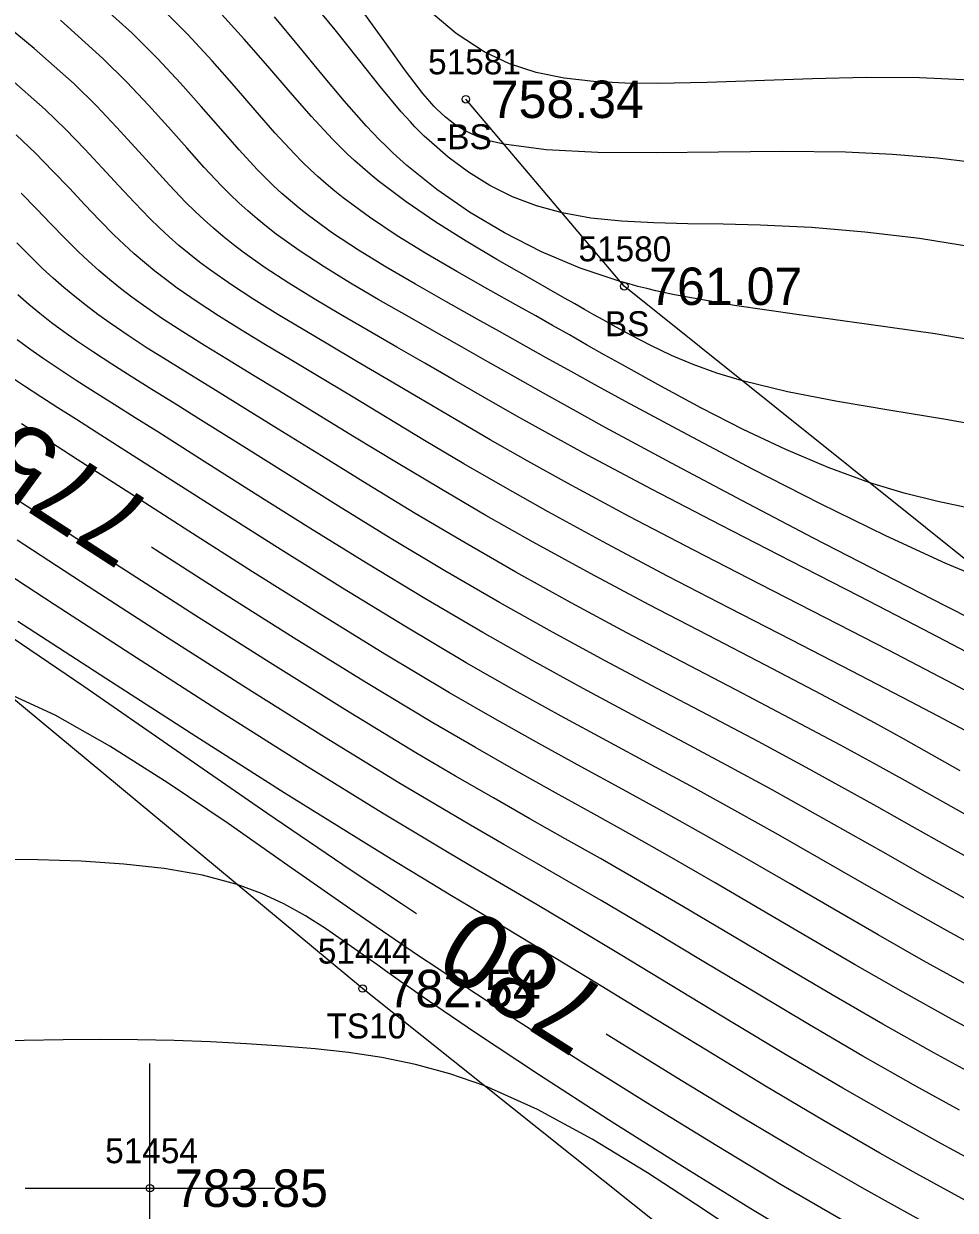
# Model space of a CAD drawing. Extents: x 1378535 to 1380697, y 997729 to 1000024.
# Drawn here: x 1379953.29 to 1379990.62, y 998733.56 to 998781.1 of the extents above; entities that cross this region are included whole.
import ezdxf

# ---------------------------------------------------------------- set-up
doc = ezdxf.new("R2010")
doc.units = 0
for name, color, linetype in [('RD_DTM_BkLn2', 7, 'Continuous'), ('RD_DTM_BkLn_txCode', 7, 'Continuous'), ('RD_DTM_Major1', 7, 'Continuous'), ('RD_DTM_Major1_Lbl', 7, 'Continuous'), ('RD_DTM_Minor1', 7, 'Continuous'), ('RD_EX_Misc', 7, 'Continuous'), ('RD_EX_Misc_txCode', 7, 'Continuous'), ('RD_EX_TX_Misc_ELEV', 7, 'Continuous'), ('RD_SMD_Locator', 7, 'Continuous')]:
    doc.layers.add(name, color=color, linetype=linetype)

msp = doc.modelspace()

# ---------------------------------------------------------------- linework, layer by layer
at = {"layer": 'RD_DTM_BkLn2'}
for points in [[(1380137.104, 998617.435), (1380114.932, 998627.982), (1380110.142, 998637.412), (1380109.582, 998648.354), (1380098.693, 998654.921), (1380088.864, 998651.688), (1380069.259, 998664.275), (1380051.712, 998676.601), (1380045.085, 998683.058), (1380025.38, 998678.361), (1380019.034, 998684.269), (1380023.868, 998692.688), (1380008.939, 998708.879), (1379966.873, 998742.441), (1379939.691, 998764.989), (1379904.79, 998796.424), (1379861.371, 998834.485), (1379829.578, 998867.997), (1379786.438, 998908.428), (1379759.831, 998933.444)], [(1380014.763, 998739.683), (1379995.467, 998756.083), (1379977.358, 998770.579), (1379971.008, 998778.071)]]:
    msp.add_lwpolyline(points, dxfattribs=at)
at = {"layer": 'RD_DTM_Major1'}
for points in [[(1379991.408, 998772.127), (1379989.19, 998772.491), (1379986.999, 998772.754), (1379984.861, 998772.929), (1379982.799, 998773.028), (1379981.321, 998773.063), (1379979.902, 998773.087), (1379978.544, 998773.121), (1379977.251, 998773.189), (1379976.024, 998773.314), (1379974.866, 998773.52), (1379973.845, 998773.801), (1379972.882, 998774.168), (1379971.974, 998774.618), (1379971.116, 998775.145), (1379970.305, 998775.746), (1379969.535, 998776.416), (1379969.345, 998776.598), (1379969.157, 998776.784), (1379968.971, 998776.974), (1379968.786, 998777.17), (1379968.602, 998777.37), (1379968.418, 998777.575), (1379967.574, 998778.578), (1379966.702, 998779.676), (1379965.773, 998780.855), (1379964.758, 998782.101)], [(1379992.409, 998756.662), (1379990.25, 998757.758), (1379987.715, 998759.057), (1379984.944, 998760.491), (1379982.074, 998761.992), (1379979.246, 998763.492), (1379976.597, 998764.924), (1379975.318, 998765.628), (1379974.116, 998766.298), (1379972.98, 998766.938), (1379971.897, 998767.552), (1379970.858, 998768.144), (1379969.85, 998768.716), (1379968.655, 998769.393), (1379967.499, 998770.054), (1379966.388, 998770.707), (1379965.331, 998771.356), (1379964.336, 998772.01), (1379963.41, 998772.673), (1379963.02, 998772.976), (1379962.643, 998773.283), (1379962.277, 998773.598), (1379961.919, 998773.923), (1379961.567, 998774.258), (1379961.218, 998774.607), (1379960.529, 998775.34), (1379959.824, 998776.127), (1379959.085, 998776.963), (1379958.292, 998777.842), (1379957.427, 998778.758), (1379956.469, 998779.705), (1379954.761, 998781.238)], [(1379991.217, 998749.311), (1379989.913, 998750.041), (1379988.628, 998750.76), (1379987.339, 998751.474), (1379986.025, 998752.191), (1379983.983, 998753.279), (1379981.859, 998754.391), (1379979.677, 998755.53), (1379977.46, 998756.696), (1379975.233, 998757.892), (1379973.018, 998759.118), (1379970.977, 998760.294), (1379968.985, 998761.476), (1379967.061, 998762.645), (1379965.222, 998763.779), (1379963.487, 998764.858), (1379961.871, 998765.859), (1379960.879, 998766.469), (1379959.946, 998767.043), (1379959.068, 998767.586), (1379958.245, 998768.106), (1379957.475, 998768.608), (1379956.754, 998769.1), (1379956.262, 998769.452), (1379955.792, 998769.806), (1379955.339, 998770.164), (1379954.9, 998770.53), (1379954.471, 998770.907), (1379954.048, 998771.298), (1379953.539, 998771.794), (1379953.021, 998772.315)], [(1379992.549, 998740.087), (1379990.492, 998741.195), (1379988.531, 998742.289), (1379986.605, 998743.394), (1379984.711, 998744.5), (1379982.845, 998745.598), (1379981.001, 998746.678), (1379979.177, 998747.729), (1379977.666, 998748.582), (1379976.148, 998749.427), (1379974.607, 998750.281), (1379973.028, 998751.164), (1379971.392, 998752.094), (1379969.684, 998753.088), (1379966.959, 998754.728), (1379964.132, 998756.48), (1379961.304, 998758.269), (1379958.574, 998760.019), (1379958.408, 998760.126)], [(1379969.033, 998745.436), (1379968.427, 998745.831), (1379967.439, 998746.483), (1379966.413, 998747.168), (1379963.041, 998749.468), (1379959.406, 998751.982), (1379955.698, 998754.54), (1379952.103, 998756.971)], [(1379989.442, 998733.041), (1379988.182, 998733.739), (1379986.894, 998734.461), (1379984.56, 998735.807), (1379982.128, 998737.248), (1379979.638, 998738.757), (1379977.129, 998740.304), (1379976.633, 998740.614)]]:
    msp.add_lwpolyline(points, dxfattribs=at)
at = {"layer": 'RD_DTM_Minor1'}
for points in [[(1379992.296, 998758.621), (1379990.242, 998759.474), (1379987.842, 998760.581), (1379985.226, 998761.863), (1379982.527, 998763.241), (1379979.875, 998764.635), (1379977.402, 998765.967), (1379976.282, 998766.58), (1379975.227, 998767.162), (1379974.229, 998767.718), (1379972.359, 998768.765), (1379971.468, 998769.263), (1379970.206, 998769.969), (1379968.987, 998770.659), (1379967.818, 998771.342), (1379966.708, 998772.024), (1379965.666, 998772.714), (1379964.7, 998773.419), (1379964.337, 998773.707), (1379963.985, 998774.001), (1379963.642, 998774.301), (1379963.307, 998774.61), (1379962.976, 998774.93), (1379962.649, 998775.261), (1379961.925, 998776.043), (1379961.185, 998776.885), (1379960.406, 998777.781), (1379959.569, 998778.724), (1379958.651, 998779.708), (1379957.632, 998780.726), (1379955.804, 998782.372)], [(1379991.646, 998755.622), (1379989.348, 998756.831), (1379986.773, 998758.16), (1379984.029, 998759.565), (1379981.226, 998761.005), (1379978.473, 998762.437), (1379975.878, 998763.818), (1379974.424, 998764.614), (1379973.056, 998765.377), (1379971.765, 998766.11), (1379970.539, 998766.814), (1379969.367, 998767.492), (1379968.238, 998768.145), (1379967.091, 998768.806), (1379965.985, 998769.447), (1379964.927, 998770.076), (1379963.921, 998770.698), (1379962.974, 998771.318), (1379962.092, 998771.943), (1379961.68, 998772.258), (1379961.282, 998772.577), (1379960.896, 998772.904), (1379960.519, 998773.241), (1379960.148, 998773.589), (1379959.781, 998773.952), (1379959.129, 998774.637), (1379958.462, 998775.37), (1379957.763, 998776.146), (1379957.016, 998776.96), (1379956.204, 998777.808), (1379955.308, 998778.686), (1379953.718, 998780.106), (1379951.922, 998781.575)], [(1379991.248, 998761.681), (1379989.924, 998761.958), (1379988.577, 998762.29), (1379987.198, 998762.703), (1379985.526, 998763.314), (1379983.826, 998764.039), (1379982.125, 998764.845), (1379980.45, 998765.701), (1379978.827, 998766.573), (1379977.283, 998767.43), (1379976.556, 998767.838), (1379975.85, 998768.237), (1379975.159, 998768.628), (1379974.48, 998769.013), (1379973.808, 998769.393), (1379973.136, 998769.772), (1379971.892, 998770.469), (1379970.653, 998771.17), (1379969.437, 998771.881), (1379968.261, 998772.605), (1379967.143, 998773.349), (1379966.1, 998774.118), (1379965.754, 998774.395), (1379965.417, 998774.678), (1379965.089, 998774.966), (1379964.768, 998775.263), (1379964.452, 998775.568), (1379964.139, 998775.883), (1379963.358, 998776.724), (1379962.564, 998777.63), (1379961.735, 998778.593), (1379960.844, 998779.606), (1379959.868, 998780.662), (1379958.782, 998781.754)], [(1379992.47, 998764.834), (1379990.249, 998765.236), (1379988.04, 998765.605), (1379985.904, 998765.967), (1379983.903, 998766.351), (1379982.099, 998766.784), (1379981.064, 998767.1), (1379980.118, 998767.444), (1379979.245, 998767.812), (1379978.427, 998768.201), (1379977.648, 998768.605), (1379976.888, 998769.02), (1379976.516, 998769.229), (1379976.141, 998769.441), (1379975.764, 998769.655), (1379975.381, 998769.873), (1379974.991, 998770.095), (1379974.592, 998770.322), (1379973.447, 998770.97), (1379972.246, 998771.658), (1379971.021, 998772.386), (1379969.801, 998773.153), (1379968.617, 998773.959), (1379967.499, 998774.805), (1379967.177, 998775.069), (1379966.863, 998775.338), (1379966.556, 998775.612), (1379966.255, 998775.892), (1379965.958, 998776.179), (1379965.665, 998776.473), (1379964.819, 998777.384), (1379963.966, 998778.361), (1379963.08, 998779.397), (1379962.132, 998780.485), (1379961.094, 998781.616)], [(1379991.672, 998775.493), (1379989.913, 998775.718), (1379988.101, 998775.866), (1379986.22, 998775.949), (1379983.697, 998775.977), (1379981.134, 998775.956), (1379978.634, 998775.931), (1379976.3, 998775.945), (1379974.233, 998776.042), (1379972.536, 998776.268), (1379971.95, 998776.413), (1379971.436, 998776.592), (1379970.98, 998776.807), (1379970.569, 998777.06), (1379970.191, 998777.355), (1379969.831, 998777.694), (1379969.741, 998777.788), (1379969.651, 998777.885), (1379969.561, 998777.985), (1379969.471, 998778.088), (1379969.381, 998778.194), (1379969.29, 998778.303), (1379968.589, 998779.217), (1379967.824, 998780.283), (1379966.968, 998781.479)], [(1379991.235, 998778.833), (1379989.182, 998778.936), (1379987.056, 998778.946), (1379984.901, 998778.897), (1379980.674, 998778.743), (1379978.69, 998778.703), (1379977.376, 998778.714), (1379976.13, 998778.779), (1379974.947, 998778.917), (1379973.824, 998779.149), (1379972.757, 998779.494), (1379971.743, 998779.973), (1379970.621, 998780.714), (1379969.524, 998781.635)], [(1379992.54, 998768.201), (1379989.812, 998768.671), (1379987.064, 998769.067), (1379984.362, 998769.432), (1379981.775, 998769.808), (1379979.37, 998770.238), (1379978.995, 998770.317), (1379978.626, 998770.399), (1379978.263, 998770.485), (1379977.904, 998770.576), (1379977.548, 998770.671), (1379977.195, 998770.771), (1379975.587, 998771.311), (1379974.035, 998771.964), (1379972.552, 998772.715), (1379971.151, 998773.551), (1379969.845, 998774.457), (1379968.649, 998775.42), (1379968.363, 998775.673), (1379968.084, 998775.929), (1379967.811, 998776.189), (1379967.544, 998776.453), (1379967.282, 998776.722), (1379967.023, 998776.996), (1379966.129, 998778.004), (1379965.239, 998779.073), (1379964.32, 998780.198), (1379963.338, 998781.37)], [(1379991.177, 998754.298), (1379990.297, 998754.768), (1379987.942, 998756.001), (1379985.417, 998757.3), (1379982.795, 998758.642), (1379980.149, 998760.004), (1379977.554, 998761.361), (1379975.081, 998762.691), (1379973.489, 998763.575), (1379971.981, 998764.433), (1379970.55, 998765.263), (1379969.19, 998766.063), (1379967.891, 998766.832), (1379966.647, 998767.568), (1379965.544, 998768.217), (1379964.485, 998768.842), (1379963.474, 998769.449), (1379962.516, 998770.044), (1379961.614, 998770.633), (1379960.772, 998771.223), (1379960.338, 998771.548), (1379959.92, 998771.878), (1379959.515, 998772.215), (1379959.12, 998772.561), (1379958.732, 998772.92), (1379958.348, 998773.294), (1379957.731, 998773.931), (1379957.1, 998774.61), (1379956.442, 998775.327), (1379955.74, 998776.078), (1379954.98, 998776.859), (1379954.147, 998777.668), (1379952.673, 998778.978)], [(1379991.022, 998752.774), (1379989.93, 998753.356), (1379988.82, 998753.943), (1379986.481, 998755.161), (1379984.051, 998756.411), (1379981.574, 998757.684), (1379979.094, 998758.969), (1379976.656, 998760.258), (1379974.302, 998761.541), (1379972.579, 998762.513), (1379970.931, 998763.47), (1379969.356, 998764.403), (1379967.853, 998765.306), (1379966.421, 998766.172), (1379965.059, 998766.994), (1379963.995, 998767.631), (1379962.98, 998768.239), (1379962.015, 998768.825), (1379961.102, 998769.395), (1379960.244, 998769.954), (1379959.443, 998770.509), (1379958.988, 998770.845), (1379958.551, 998771.183), (1379958.128, 998771.529), (1379957.717, 998771.883), (1379957.314, 998772.25), (1379956.915, 998772.632), (1379956.333, 998773.222), (1379955.74, 998773.848), (1379955.122, 998774.506), (1379954.466, 998775.195), (1379953.759, 998775.911), (1379952.986, 998776.651)], [(1379990.812, 998751.16), (1379989.688, 998751.803), (1379988.551, 998752.443), (1379987.381, 998753.088), (1379985.258, 998754.226), (1379983.02, 998755.397), (1379980.706, 998756.597), (1379978.357, 998757.821), (1379976.01, 998759.065), (1379973.707, 998760.324), (1379971.811, 998761.4), (1379969.981, 998762.47), (1379968.226, 998763.521), (1379966.55, 998764.539), (1379964.963, 998765.511), (1379963.47, 998766.423), (1379962.439, 998767.049), (1379961.462, 998767.641), (1379960.54, 998768.206), (1379959.672, 998768.751), (1379958.858, 998769.281), (1379958.098, 998769.804), (1379957.624, 998770.148), (1379957.17, 998770.495), (1379956.733, 998770.847), (1379956.307, 998771.207), (1379955.891, 998771.58), (1379955.48, 998771.968), (1379954.934, 998772.51), (1379954.379, 998773.083), (1379953.802, 998773.684), (1379953.193, 998774.311)], [(1379991.802, 998747.315), (1379990.323, 998748.136), (1379988.891, 998748.939), (1379987.484, 998749.729), (1379986.078, 998750.513), (1379984.653, 998751.296), (1379982.718, 998752.335), (1379980.72, 998753.389), (1379978.673, 998754.468), (1379976.588, 998755.576), (1379974.477, 998756.721), (1379972.352, 998757.911), (1379970.165, 998759.183), (1379968.007, 998760.478), (1379965.908, 998761.768), (1379963.898, 998763.021), (1379962.009, 998764.208), (1379960.269, 998765.299), (1379959.319, 998765.89), (1379958.43, 998766.443), (1379957.597, 998766.964), (1379956.818, 998767.458), (1379956.09, 998767.934), (1379955.409, 998768.395), (1379954.899, 998768.757), (1379954.412, 998769.119), (1379953.945, 998769.482), (1379953.493, 998769.852), (1379953.052, 998770.231)], [(1379990.993, 998746.068), (1379989.395, 998746.96), (1379987.846, 998747.836), (1379986.325, 998748.699), (1379984.811, 998749.553), (1379983.282, 998750.402), (1379981.455, 998751.393), (1379979.583, 998752.393), (1379977.668, 998753.412), (1379975.712, 998754.463), (1379973.718, 998755.557), (1379971.688, 998756.704), (1379969.36, 998758.07), (1379967.034, 998759.479), (1379964.757, 998760.891), (1379962.572, 998762.266), (1379960.526, 998763.563), (1379958.663, 998764.742), (1379957.759, 998765.311), (1379956.915, 998765.841), (1379956.128, 998766.338), (1379955.394, 998766.808), (1379954.708, 998767.256), (1379954.066, 998767.69), (1379953.536, 998768.062), (1379953.032, 998768.43)], [(1379991.945, 998743.841), (1379990.171, 998744.815), (1379988.461, 998745.778), (1379986.798, 998746.728), (1379985.164, 998747.667), (1379983.541, 998748.594), (1379981.914, 998749.509), (1379980.193, 998750.454), (1379978.442, 998751.401), (1379976.655, 998752.364), (1379974.827, 998753.358), (1379972.951, 998754.397), (1379971.023, 998755.497), (1379968.559, 998756.956), (1379966.066, 998758.479), (1379963.607, 998760.015), (1379961.243, 998761.513), (1379959.038, 998762.921), (1379957.053, 998764.189), (1379956.198, 998764.732), (1379955.403, 998765.237), (1379954.663, 998765.708), (1379953.973, 998766.153), (1379953.329, 998766.575), (1379952.726, 998766.981)], [(1379991.22, 998742.52), (1379989.349, 998743.555), (1379987.53, 998744.589), (1379985.752, 998745.617), (1379984.003, 998746.634), (1379982.271, 998747.636), (1379980.546, 998748.618), (1379978.93, 998749.517), (1379977.297, 998750.412), (1379975.635, 998751.32), (1379973.932, 998752.258), (1379972.176, 998753.243), (1379970.355, 998754.292), (1379967.759, 998755.842), (1379965.099, 998757.479), (1379962.456, 998759.141), (1379959.911, 998760.764), (1379957.545, 998762.285), (1379955.437, 998763.641), (1379954.637, 998764.153), (1379953.894, 998764.63), (1379953.203, 998765.074)], [(1379991.673, 998738.829), (1379989.764, 998739.865), (1379987.719, 998741.015), (1379985.689, 998742.191), (1379983.678, 998743.378), (1379981.691, 998744.559), (1379979.732, 998745.719), (1379977.807, 998746.843), (1379976.4, 998747.649), (1379974.995, 998748.444), (1379973.573, 998749.247), (1379972.114, 998750.076), (1379970.599, 998750.949), (1379969.009, 998751.885), (1379966.157, 998753.616), (1379963.162, 998755.486), (1379960.145, 998757.404), (1379957.23, 998759.282), (1379954.538, 998761.03), (1379952.191, 998762.56)], [(1379990.797, 998737.568), (1379989.039, 998738.531), (1379986.916, 998739.735), (1379984.783, 998740.981), (1379982.654, 998742.249), (1379980.543, 998743.516), (1379978.465, 998744.761), (1379976.434, 998745.963), (1379975.133, 998746.719), (1379973.839, 998747.465), (1379972.531, 998748.218), (1379971.19, 998748.993), (1379969.796, 998749.81), (1379968.33, 998750.684), (1379965.348, 998752.511), (1379962.183, 998754.5), (1379958.978, 998756.548), (1379955.878, 998758.551), (1379953.028, 998760.406)], [(1379991.503, 998735.447), (1379989.921, 998736.304), (1379988.318, 998737.191), (1379986.122, 998738.448), (1379983.888, 998739.764), (1379981.641, 998741.113), (1379977.2, 998743.802), (1379975.056, 998745.088), (1379973.865, 998745.792), (1379972.682, 998746.487), (1379971.49, 998747.187), (1379970.268, 998747.908), (1379968.999, 998748.664), (1379967.664, 998749.471), (1379964.551, 998751.396), (1379961.213, 998753.506), (1379957.812, 998755.687), (1379954.512, 998757.825), (1379951.476, 998759.806)], [(1379991.88, 998733.487), (1379990.471, 998734.255), (1379989.051, 998735.034), (1379987.605, 998735.844), (1379985.343, 998737.15), (1379983.012, 998738.534), (1379980.647, 998739.965), (1379978.279, 998741.411), (1379975.94, 998742.841), (1379973.664, 998744.224), (1379972.588, 998744.872), (1379971.519, 998745.513), (1379970.441, 998746.16), (1379969.338, 998746.824), (1379968.195, 998747.516), (1379966.997, 998748.25), (1379963.728, 998750.289), (1379960.194, 998752.534), (1379956.577, 998754.863), (1379953.058, 998757.151)], [(1379986.113, 998733.144), (1379983.648, 998734.581), (1379981.061, 998736.132), (1379978.405, 998737.761), (1379975.736, 998739.435), (1379973.108, 998741.119), (1379970.576, 998742.778), (1379969.842, 998743.267), (1379969.117, 998743.754), (1379968.397, 998744.241), (1379967.676, 998744.733), (1379966.95, 998745.232), (1379966.215, 998745.741), (1379963.88, 998747.376), (1379961.48, 998749.049), (1379959.081, 998750.669), (1379956.749, 998752.148), (1379954.551, 998753.395), (1379952.553, 998754.32)], [(1379985.166, 998731.967), (1379982.431, 998733.616), (1379979.582, 998735.377), (1379976.724, 998737.183), (1379973.961, 998738.967), (1379971.397, 998740.663), (1379969.138, 998742.203), (1379968.787, 998742.449), (1379968.446, 998742.688), (1379968.116, 998742.921), (1379967.796, 998743.149), (1379967.484, 998743.371), (1379967.18, 998743.588), (1379966.285, 998744.225), (1379965.428, 998744.814), (1379964.582, 998745.351), (1379963.721, 998745.832), (1379962.818, 998746.253), (1379961.846, 998746.611), (1379960.452, 998746.979), (1379958.927, 998747.247), (1379957.3, 998747.43), (1379955.6, 998747.542), (1379953.858, 998747.597), (1379952.103, 998747.609)], [(1379982.754, 998732.104), (1379980.524, 998733.604), (1379978.287, 998735.059), (1379976.066, 998736.408), (1379973.884, 998737.588), (1379971.765, 998738.538), (1379970.364, 998739.028), (1379968.994, 998739.402), (1379967.646, 998739.679), (1379966.31, 998739.88), (1379964.978, 998740.025), (1379963.639, 998740.133), (1379962.214, 998740.226), (1379960.774, 998740.3), (1379959.318, 998740.354), (1379957.849, 998740.388), (1379956.368, 998740.401), (1379954.875, 998740.392), (1379953.31, 998740.36), (1379951.747, 998740.309)]]:
    msp.add_lwpolyline(points, dxfattribs=at)
at = {"layer": 'RD_EX_Misc'}
for p, q in [((1379958.35, 998729.442), (1379958.35, 998739.442)), ((1379953.35, 998734.442), (1379963.35, 998734.442))]:
    msp.add_line(p, q, dxfattribs=at)
at = {"layer": 'RD_SMD_Locator'}
for centre in [(1379971.008, 998778.071), (1379977.358, 998770.579), (1379966.873, 998742.441), (1379958.35, 998734.442)]:
    msp.add_circle(centre, 0.15, dxfattribs=at)

# ---------------------------------------------------------------- texts
at = {"layer": 'RD_DTM_BkLn_txCode'}
for s, p in [('51581', (1379969.496, 998779.071)), ('-BS', (1379969.819, 998776.071)), ('51580', (1379975.523, 998771.579)), ('BS', (1379976.578, 998768.579)), ('51444', (1379965.078, 998743.441)), ('TS10', (1379965.424, 998740.441))]:
    msp.add_text(s, height=1, dxfattribs=at).set_placement(p)
at = {"layer": 'RD_DTM_Major1_Lbl'}
for s, rotation, p in [('775', 147.0508, (1379958.717, 998761.71)), ('780', 147.606, (1379976.917, 998742.187))]:
    msp.add_text(s, height=3, rotation=rotation, dxfattribs=at).set_placement(p)
at = {"layer": 'RD_EX_Misc_txCode'}
msp.add_text('51454', height=1, dxfattribs=at).set_placement((1379956.555, 998735.442))
at = {"layer": 'RD_EX_TX_Misc_ELEV'}
for s, p in [('758.34', (1379972.008, 998777.321)), ('761.07', (1379978.358, 998769.829)), ('782.54', (1379967.873, 998741.691)), ('783.85', (1379959.35, 998733.692))]:
    msp.add_text(s, height=1.5, dxfattribs=at).set_placement(p)

doc.saveas('drawing.dxf')
